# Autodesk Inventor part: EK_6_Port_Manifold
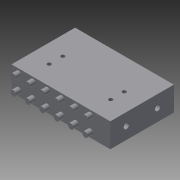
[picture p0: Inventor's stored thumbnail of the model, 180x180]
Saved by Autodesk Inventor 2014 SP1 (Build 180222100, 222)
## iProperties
Created: 2014-02
Part Number: EK_6_Port_Manifold
Material: Generic
Document SubType Name: Modeling
Designer: User
Density: 0.947274 g/cm^3
Appearance: Default
Mass: 229.518 g
Surface Area: 357.978 cm^2
Volume: 242.293 cm^3
Author: User
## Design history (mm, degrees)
node "EK_6_Port_Manifold.ipt1"
node "Cut-Extrude1"
node "Base1"
